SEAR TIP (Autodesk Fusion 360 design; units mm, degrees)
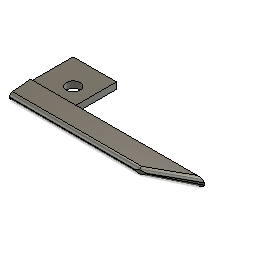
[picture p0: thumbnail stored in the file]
sketch "Sketch1" plane through (0, 0, 0) normal (0, 1, 0) x axis (1, 0, 0)
  line L1 (8, 0) -> (0, 0)
  line L2 (8, -7.83) -> (8, 0)
  line L3 (32, -7.83) -> (8, -7.83)
  line L4 (0, -11.75) -> (0, 0)
  line L5 (24, -11.75) -> (0, -11.75)
  line L6 (32, -7.83) -> (24, -11.75)
  curve K1 (32, -7.83) -> (24, -11.75)
  point P1 (0, 0)
  point P2 (0, 0)
  point P6 (0, 0)
  point P3 (8, 0)
  point P4 (8, -7.83)
  point P5 (32, -7.83)
  point P7 (0, -11.75)
  point P8 (24, -11.75)
  coincident P1 P2
  horizontal L1
  perpendicular L1 L2
  perpendicular L2 L3
  coincident P1 P6
  perpendicular L1 L4
  perpendicular L4 L5
  dimension "d1" distance P2 P3 = 8
  dimension "d2" distance P3 P4 = 7.83
  dimension "d3" distance P4 P5 = 24
  dimension "d4" distance P6 P7 = 11.75
  dimension "d18" distance P7 P8 = 24
extrude "Extrude1" new body sketch "Sketch1" along normal blind 1.2
work_plane "WorkPlane1" AlongDistance 0
split "Split1"
hole "Hole1" HoleDepth 2 HoleDiameter 2.5 TipAngle 180 RefDim1 3.98 RefDim2 4.7
draft "Draft1" Angle1 5 Angle2 0
fillet "Fillet4" radius 4
fillet "Fillet3" radius 0.6
combine "Combine1"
